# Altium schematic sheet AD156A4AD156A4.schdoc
size 127 x 101 mm
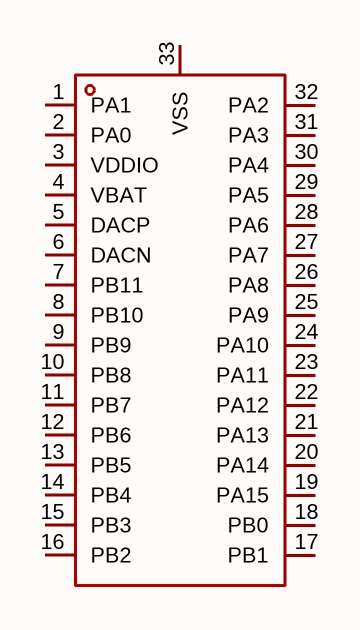
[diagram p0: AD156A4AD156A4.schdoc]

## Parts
U?  ad156a4  [WQFN-32_L4.0-W4.0-P0.40-TL-EP2.7]  (value not drawn)

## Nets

Not connected (* = marked no-connect by the designer): U? 1(PA1) 2(PA0) 3(VDDIO) 4(VBAT) 5(DACP) 6(DACN) 7(PB11) 8(PB10) 9(PB9) 10(PB8) 11(PB7) 12(PB6) 13(PB5) 14(PB4) 15(PB3) 16(PB2) 17(PB1) 18(PB0) 19(PA15) 20(PA14) 21(PA13) 22(PA12) 23(PA11) 24(PA10) 25(PA9) 26(PA8) 27(PA7) 28(PA6) 29(PA5) 30(PA4) 31(PA3) 32(PA2) 33(VSS)

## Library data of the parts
U? = ad156a4: CPU内核:-;CPU最大主频:120MHz;CPU位数:32bit;; Manufacturer: JL(杰理); AddInBom: yes; ModelId: 027a0d4fd37643a08048004d73af3ade; ModelTransform: 158.267,158.267,0,0,0,0,0,0.001,0; CPU Maximum Speed: 120MHz; Core Size: 32bit; Number of I/O: 28; ADC (Bit): 10bit; Oscillator Type: 内置; Voltage - Supply: 2V~5.5V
